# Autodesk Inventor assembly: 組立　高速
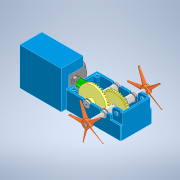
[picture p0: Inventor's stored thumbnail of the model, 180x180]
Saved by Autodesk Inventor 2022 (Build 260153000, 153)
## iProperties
Created: 2024-12
Part Number: 組立　高速
Document SubType Name: Assembly
Designer: jsat7
Author: jsat7
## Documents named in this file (17)
- C:\Users\jsat7\OneDrive\デスクトップ\卒論2024\３DCAD\自在ギヤボックス\組立図\組立　高速.iam
- C:\Users\jsat7\OneDrive\デスクトップ\卒論2024\３DCAD\自在ギヤボックス - コピー\部品図\ボックス　下.ipt
- C:\Users\jsat7\OneDrive\デスクトップ\卒論2024\３DCAD\自在ギヤボックス - コピー\部品図\B3.ipt
- C:\Users\jsat7\OneDrive\デスクトップ\卒論2024\３DCAD\自在ギヤボックス - コピー\部品図\B4.ipt
- C:\Users\jsat7\OneDrive\デスクトップ\卒論2024\３DCAD\自在ギヤボックス - コピー\部品図\B6.ipt
- C:\Users\jsat7\OneDrive\デスクトップ\卒論2024\３DCAD\自在ギヤボックス - コピー\部品図\丸棒.ipt
- C:\Users\jsat7\OneDrive\デスクトップ\卒論2024\３DCAD\自在ギヤボックス - コピー\部品図\クラウンギア.iam
- C:\Users\jsat7\OneDrive\デスクトップ\卒論2024\３DCAD\自在ギヤボックス - コピー\部品図\モーター　ピニオンギア.iam
- C:\Users\jsat7\OneDrive\デスクトップ\卒論2024\３DCAD\自在ギヤボックス - コピー\部品図\モーター　箱.ipt
- C:\Users\jsat7\OneDrive\デスクトップ\卒論2024\３DCAD\自在ギヤボックス - コピー\部品図\ピニオンギア.ipt
- C:\Users\jsat7\OneDrive\デスクトップ\卒論2024\３DCAD\自在ギヤボックス - コピー\部品図\六角シャフト.ipt
- C:\Users\jsat7\OneDrive\デスクトップ\卒論2024\３DCAD\自在ギヤボックス - コピー\部品図\B7.ipt
- C:\Users\jsat7\OneDrive\デスクトップ\卒論2024\３DCAD\自在ギヤボックス\部品図\特殊平ギア.ipt
- C:\Users\jsat7\OneDrive\デスクトップ\卒論2024\３DCAD\自在ギヤボックス\部品図\固定器具.ipt
- C:\Users\jsat7\OneDrive\デスクトップ\卒論2024\３DCAD\自在ギヤボックス\部品図\B1.ipt
- C:\Users\jsat7\OneDrive\デスクトップ\卒論2024\３DCAD\自在ギヤボックス\部品図\B2.ipt
- C:\Users\jsat7\OneDrive\デスクトップ\卒論2024\３DCAD\自在ギヤボックス\部品図\プロペラ.ipt
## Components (15 placed, 13 different names)
1. B4:1 — メイト:2, フラッシュ:2, メイト:3
2. B6:1 — メイト:1, メイト:28, メイト:29, フラッシュ:13
3. 丸棒:1 — メイト:3, メイト:5, メイト:28, メイト:33
4. クラウンギア:1 [sub-assembly] — メイト:5, 回転:1, メイト:29, メイト:32, 回転:2
5. モーター　ピニオンギア:1 [sub-assembly] — フラッシュ:5, フラッシュ:6, メイト:13, メイト:14, フラッシュ:8
6. 平歯車1:1 — メイト:14, フラッシュ:8, 回転:1, 角度:1
7. 六角シャフト:1 — メイト:26, リジッド:1, リジッド:2, メイト:35, リジッド:3, リジッド:4
8. B3:1 — メイト:24, フラッシュ:11, メイト:30
9. B7:1 — メイト:25, フラッシュ:12, メイト:26
10. 平歯車1:2 — メイト:30, リジッド:1, メイト:31, 回転:2
11. 固定器具:1 — メイト:31, リジッド:2, メイト:34
12. B1:1 — メイト:32, メイト:33
13. B2:1 — メイト:34, メイト:35
14. プロペラ:1 — リジッド:3
15. プロペラ:2 — リジッド:4
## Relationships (31: Mate 17, Flush 7, WeldJoint 4, RelateRotation 2, Angle 1)
- メイト:1 [Mate]: B6:1
- メイト:2 [Mate]: B4:1
- フラッシュ:2 [Flush]: B4:1
- メイト:3 [Mate]: B4:1 ↔ 丸棒:1
- メイト:5 [Mate]: 丸棒:1 ↔ クラウンギア:1
- フラッシュ:5 [Flush]: モーター　ピニオンギア:1
- フラッシュ:6 [Flush]: モーター　ピニオンギア:1
- メイト:13 [Mate]: モーター　ピニオンギア:1
- メイト:14 [Mate]: モーター　ピニオンギア:1 ↔ 平歯車1:1
- フラッシュ:8 [Flush]: モーター　ピニオンギア:1 ↔ 平歯車1:1
- 回転:1 [RelateRotation]: クラウンギア:1 ↔ 平歯車1:1
- 角度:1 [Angle]: 平歯車1:1
- メイト:24 [Mate]: B3:1
- フラッシュ:11 [Flush]: B3:1
- メイト:25 [Mate]: B7:1
- フラッシュ:12 [Flush]: B7:1
- メイト:26 [Mate]: 六角シャフト:1 ↔ B7:1
- メイト:28 [Mate]: B6:1 ↔ 丸棒:1
- メイト:29 [Mate]: B6:1 ↔ クラウンギア:1
- フラッシュ:13 [Flush]: B6:1
- メイト:30 [Mate]: B3:1 ↔ 平歯車1:2
- リジッド:1 [WeldJoint]: 六角シャフト:1 ↔ 平歯車1:2
- メイト:31 [Mate]: 平歯車1:2 ↔ 固定器具:1
- リジッド:2 [WeldJoint]: 六角シャフト:1 ↔ 固定器具:1
- メイト:32 [Mate]: クラウンギア:1 ↔ B1:1
- メイト:33 [Mate]: 丸棒:1 ↔ B1:1
- メイト:34 [Mate]: 固定器具:1 ↔ B2:1
- メイト:35 [Mate]: 六角シャフト:1 ↔ B2:1
- 回転:2 [RelateRotation]: クラウンギア:1 ↔ 平歯車1:2
- リジッド:3 [WeldJoint]: 六角シャフト:1 ↔ プロペラ:1
- リジッド:4 [WeldJoint]: 六角シャフト:1 ↔ プロペラ:2
